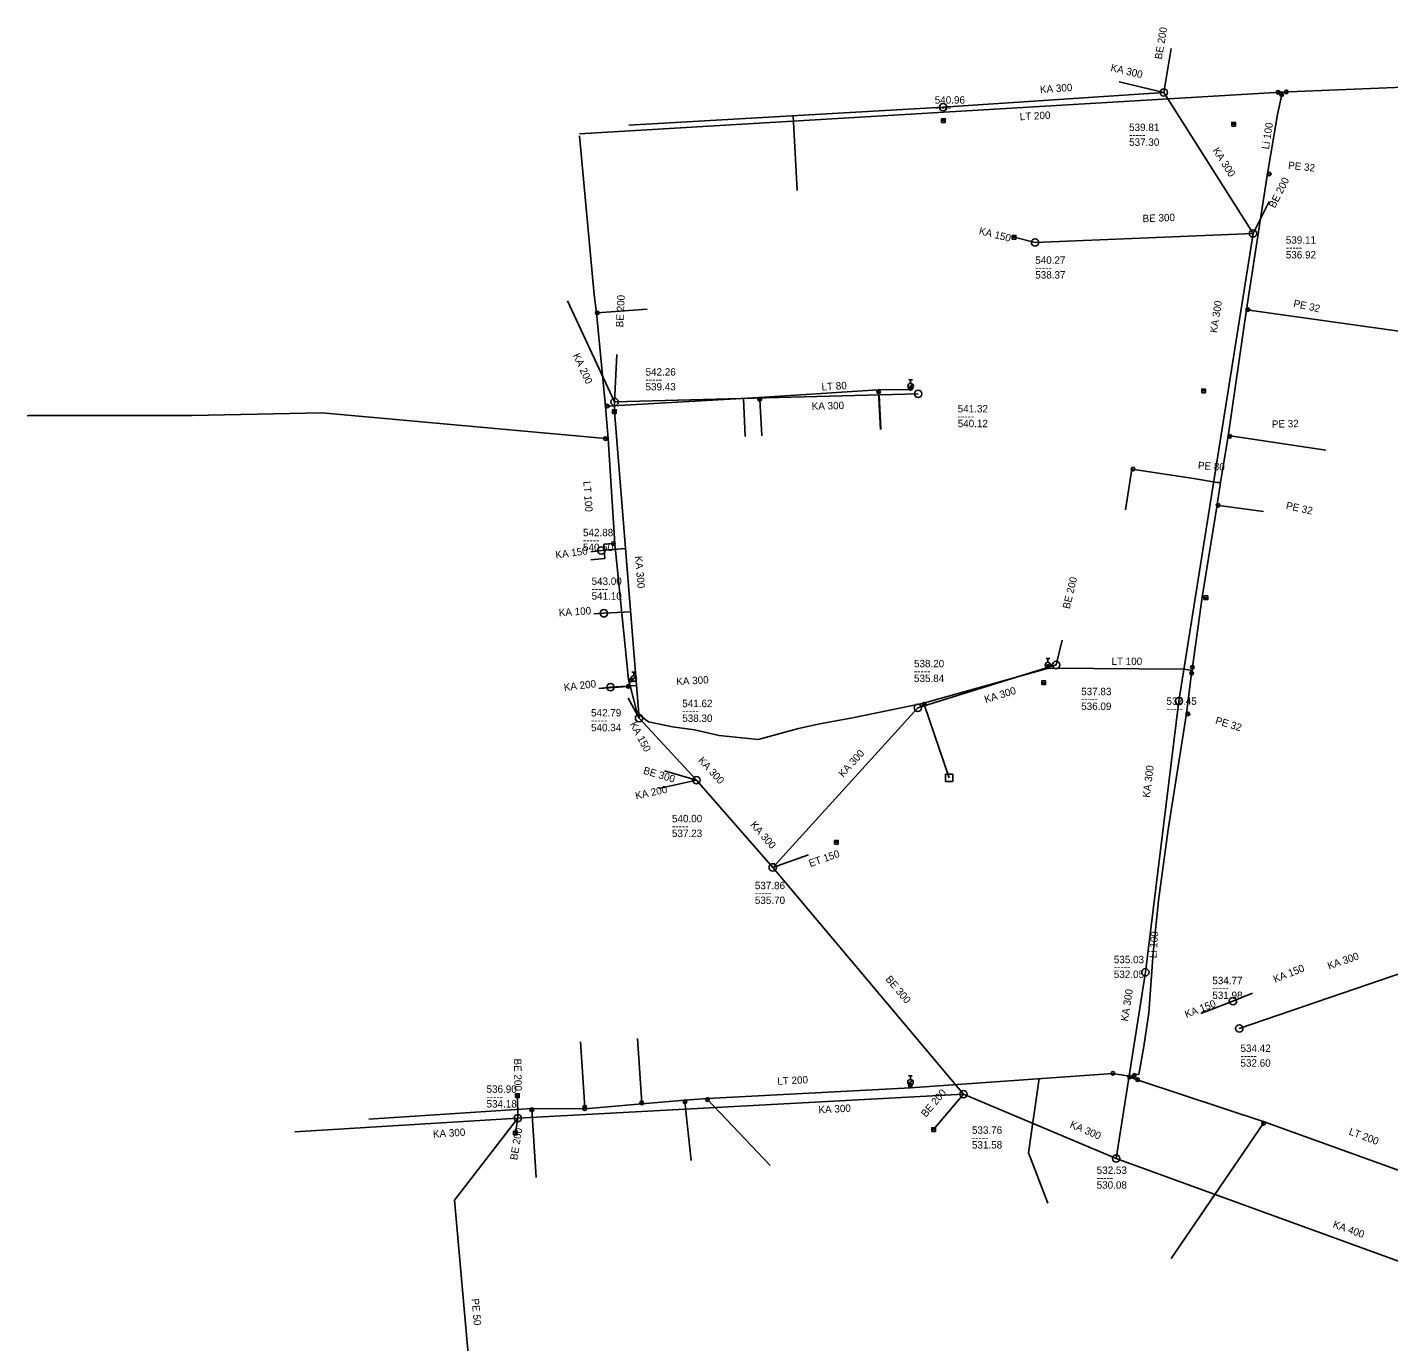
# Model space of a CAD drawing. Extents: x -769542 to -769122, y -1181691 to -1181360.
# Drawn here: x -769542.3 to -769357.9, y -1181565.1 to -1181387.2 of the extents above; entities that cross this region are included whole.
import ezdxf

# ---------------------------------------------------------------- set-up
doc = ezdxf.new("R2010")
doc.units = 0
for name, color, linetype in [('Level 19', 7, 'Continuous'), ('Level 20', 7, 'Continuous'), ('Level 21', 7, 'Continuous'), ('Level 24', 7, 'Continuous'), ('Level 26', 7, 'Continuous'), ('Level 29', 7, 'Continuous'), ('Level 40', 7, 'Continuous'), ('Level 41', 7, 'Continuous'), ('Level 44', 7, 'Continuous'), ('Level 45', 7, 'Continuous'), ('Level 46', 7, 'Continuous')]:
    doc.layers.add(name, color=color, linetype=linetype)

msp = doc.modelspace()

# ---------------------------------------------------------------- linework, layer by layer
at = {"layer": 'Level 19'}
for p, q in [((-769374.37, -1181406.99), (-769374.14, -1181407.02)), ((-769374.14, -1181407.02), (-769373.77, -1181407.06)), ((-769465.11, -1181425.84), (-769458.35, -1181425.35)), ((-769377.2, -1181425.36), (-769377.02, -1181425.4)), ((-769377.02, -1181425.4), (-769376.52, -1181425.51)), ((-769465.22, -1181425.84), (-769465.11, -1181425.84)), ((-769376.52, -1181425.51), (-769354.33, -1181428.62)), ((-769427.08, -1181436.27), (-769427.02, -1181436.51)), ((-769427.02, -1181436.51), (-769426.77, -1181441.63)), ((-769443.19, -1181437.28), (-769443.11, -1181437.54)), ((-769443.11, -1181437.54), (-769442.84, -1181442.46)), ((-769379.67, -1181442.54), (-769379.46, -1181442.54)), ((-769379.46, -1181442.54), (-769379.11, -1181442.53)), ((-769379.11, -1181442.53), (-769366.44, -1181444.44)), ((-769392.73, -1181446.98), (-769393.6, -1181452.52)), ((-769384.63, -1181448.22), (-769392.73, -1181446.98)), ((-769381.17, -1181448.78), (-769384.63, -1181448.22)), ((-769380.71, -1181448.81), (-769381.17, -1181448.78)), ((-769381.18, -1181451.84), (-769381.04, -1181451.87)), ((-769381.04, -1181451.87), (-769380.59, -1181451.97)), ((-769380.59, -1181451.97), (-769374.91, -1181452.73)), ((-769462.94, -1181457.07), (-769464.22, -1181457.16)), ((-769464.22, -1181457.16), (-769464.08, -1181459.08)), ((-769462.72, -1181457.08), (-769462.94, -1181457.07)), ((-769464.08, -1181459.08), (-769465.96, -1181459.25)), ((-769460.91, -1181476.41), (-769464.9, -1181476.7)), ((-769460.66, -1181476.32), (-769460.91, -1181476.41)), ((-769420.88, -1181478.68), (-769420.83, -1181478.83)), ((-769420.83, -1181478.83), (-769417.45, -1181488.77)), ((-769385.31, -1181480.09), (-769385.16, -1181480.13)), ((-769385.16, -1181480.13), (-769384.8, -1181480.24)), ((-769466.81, -1181533.35), (-769467.36, -1181524.5)), ((-769459.08, -1181532.77), (-769459.65, -1181524.04)), ((-769405.27, -1181529.49), (-769406.72, -1181539.56)), ((-769450.17, -1181532.2), (-769450.19, -1181532.33)), ((-769450.19, -1181532.33), (-769441.69, -1181541.27)), ((-769474, -1181533.53), (-769473.97, -1181533.72)), ((-769473.97, -1181533.72), (-769473.39, -1181542.86)), ((-769466.81, -1181533.35), (-769466.8, -1181533.57)), ((-769459.07, -1181532.92), (-769459.08, -1181532.77)), ((-769453.23, -1181532.43), (-769453.23, -1181532.62)), ((-769453.23, -1181532.62), (-769452.39, -1181540.56)), ((-769374.88, -1181535.54), (-769387.4, -1181553.86)), ((-769374.78, -1181535.36), (-769374.88, -1181535.54)), ((-769406.72, -1181539.56), (-769404.11, -1181546.34))]:
    msp.add_line(p, q, dxfattribs=at)
at = {"layer": 'Level 20'}
for p, q in [((-769321.1, -1181393.86), (-769371.45, -1181395.91)), ((-769372.37, -1181395.94), (-769372.92, -1181395.97)), ((-769372.37, -1181395.94), (-769372.42, -1181396.31)), ((-769371.8, -1181395.93), (-769372.37, -1181395.94)), ((-769371.45, -1181395.91), (-769371.8, -1181395.93)), ((-769373.3, -1181395.99), (-769467.51, -1181401.59)), ((-769372.92, -1181395.97), (-769373.3, -1181395.99)), ((-769372.42, -1181396.31), (-769373.01, -1181398.97)), ((-769373.01, -1181398.97), (-769374.37, -1181406.99)), ((-769465.53, -1181423.39), (-769467.51, -1181401.88)), ((-769374.37, -1181406.99), (-769377.2, -1181425.36)), ((-769465.22, -1181425.84), (-769465.53, -1181423.39)), ((-769377.2, -1181425.36), (-769379.67, -1181442.54)), ((-769464, -1181438.5), (-769465.22, -1181425.84)), ((-769443.19, -1181437.28), (-769427.08, -1181436.27)), ((-769427.08, -1181436.27), (-769422.72, -1181436.2)), ((-769422.72, -1181436.2), (-769422.68, -1181436.06)), ((-769422.68, -1181436.06), (-769422.68, -1181435.76)), ((-769463.77, -1181438.45), (-769443.19, -1181437.28)), ((-769542.3, -1181439.77), (-769542.1, -1181439.75)), ((-769542.1, -1181439.75), (-769519.98, -1181439.75)), ((-769519.98, -1181439.75), (-769502.36, -1181439.36)), ((-769502.36, -1181439.36), (-769464, -1181442.85)), ((-769464, -1181438.5), (-769463.77, -1181438.45)), ((-769463.65, -1181442.87), (-769464, -1181438.5)), ((-769464, -1181442.85), (-769463.65, -1181442.87)), ((-769463.65, -1181442.87), (-769462.72, -1181457.08)), ((-769379.67, -1181442.54), (-769380.71, -1181448.81)), ((-769380.71, -1181448.81), (-769381.18, -1181451.84)), ((-769381.18, -1181451.84), (-769383.2, -1181464.3)), ((-769462.72, -1181457.08), (-769460.86, -1181475.45)), ((-769383.2, -1181464.3), (-769384.51, -1181473.81)), ((-769419.81, -1181478.36), (-769404.02, -1181473.94)), ((-769404.1, -1181473.72), (-769404.08, -1181473.5)), ((-769404.02, -1181473.94), (-769404.1, -1181473.72)), ((-769404.02, -1181473.94), (-769385.64, -1181474.05)), ((-769384.57, -1181474.23), (-769385.64, -1181474.05)), ((-769384.62, -1181474.61), (-769385.31, -1181480.09)), ((-769384.57, -1181474.23), (-769384.62, -1181474.61)), ((-769384.51, -1181473.81), (-769384.57, -1181474.23)), ((-769460.86, -1181475.45), (-769460.66, -1181476.32)), ((-769460.86, -1181475.45), (-769460.52, -1181475.54)), ((-769460.66, -1181476.32), (-769459.71, -1181480.03)), ((-769460.52, -1181475.54), (-769460.18, -1181475.34)), ((-769420.88, -1181478.68), (-769430.57, -1181480.65)), ((-769420.88, -1181478.68), (-769419.81, -1181478.36)), ((-769458.15, -1181481.19), (-769459.71, -1181480.03)), ((-769430.57, -1181480.65), (-769434.95, -1181481.48)), ((-769385.31, -1181480.09), (-769387.82, -1181495.78)), ((-769454.93, -1181481.86), (-769458.15, -1181481.19)), ((-769451.93, -1181482.29), (-769454.93, -1181481.86)), ((-769448.59, -1181483.04), (-769451.93, -1181482.29)), ((-769437.84, -1181482.12), (-769443.3, -1181483.59)), ((-769434.95, -1181481.48), (-769437.84, -1181482.12)), ((-769443.3, -1181483.59), (-769448.59, -1181483.04)), ((-769387.82, -1181495.78), (-769389.13, -1181505.37)), ((-769389.13, -1181505.37), (-769389.84, -1181512.46)), ((-769389.84, -1181512.46), (-769390.4, -1181520.58)), ((-769390.4, -1181520.58), (-769391.1, -1181525.13)), ((-769391.1, -1181525.13), (-769391.76, -1181528.93)), ((-769422.73, -1181530.39), (-769422.7, -1181529.99)), ((-769422.71, -1181530.75), (-769422.73, -1181530.39)), ((-769422.71, -1181530.75), (-769395.28, -1181528.78)), ((-769395.28, -1181528.78), (-769393.37, -1181529.12)), ((-769393.37, -1181529.12), (-769393.03, -1181529.26)), ((-769393.03, -1181529.26), (-769392.5, -1181529.47)), ((-769392.38, -1181529.07), (-769392.5, -1181529.47)), ((-769392.5, -1181529.47), (-769391.95, -1181529.65)), ((-769392.25, -1181528.88), (-769392.38, -1181529.07)), ((-769391.76, -1181528.93), (-769392.25, -1181528.88)), ((-769391.95, -1181529.65), (-769391.6, -1181529.78)), ((-769391.6, -1181529.78), (-769374.78, -1181535.36)), ((-769453.23, -1181532.43), (-769450.17, -1181532.2)), ((-769450.17, -1181532.2), (-769422.71, -1181530.75)), ((-769496.05, -1181534.97), (-769474, -1181533.53)), ((-769474, -1181533.53), (-769466.8, -1181533.57)), ((-769466.8, -1181533.57), (-769459.06, -1181532.92)), ((-769459.06, -1181532.92), (-769453.23, -1181532.43)), ((-769374.78, -1181535.36), (-769346.68, -1181545.48))]:
    msp.add_line(p, q, dxfattribs=at)
at = {"layer": 'Level 21'}
for p, q in [((-769422.974, -1181435.991), (-769422.384, -1181435.528)), ((-769422.93, -1181434.885), (-769422.43, -1181434.885)), ((-769422.68, -1181435.385), (-769422.68, -1181434.885)), ((-769404.374, -1181473.731), (-769403.784, -1181473.268)), ((-769404.33, -1181472.625), (-769403.83, -1181472.625)), ((-769404.08, -1181473.125), (-769404.08, -1181472.625)), ((-769460.474, -1181475.571), (-769459.884, -1181475.108)), ((-769460.43, -1181474.465), (-769459.93, -1181474.465)), ((-769460.18, -1181474.965), (-769460.18, -1181474.465)), ((-769422.994, -1181530.221), (-769422.404, -1181529.758)), ((-769422.95, -1181529.115), (-769422.45, -1181529.115)), ((-769422.7, -1181529.615), (-769422.7, -1181529.115))]:
    msp.add_line(p, q, dxfattribs=at)
for centre in [(-769422.68, -1181435.76), (-769404.08, -1181473.5), (-769460.18, -1181475.34), (-769422.7, -1181529.99)]:
    msp.add_circle(centre, 0.375, dxfattribs=at)
at = {"layer": 'Level 26'}
for centre in [(-769372.92, -1181395.97), (-769371.8, -1181395.93), (-769372.42, -1181396.31), (-769374.14, -1181407.02), (-769377.02, -1181425.4), (-769377.02, -1181425.4), (-769465.11, -1181425.84), (-769427.02, -1181436.51), (-769422.68, -1181436.06), (-769463.77, -1181438.45), (-769443.11, -1181437.54), (-769464, -1181442.85), (-769379.46, -1181442.54), (-769392.55, -1181446.99), (-769381.04, -1181451.87), (-769462.94, -1181457.07), (-769404.1, -1181473.72), (-769384.62, -1181474.61), (-769384.51, -1181473.81), (-769460.91, -1181476.41), (-769460.52, -1181475.54), (-769420.83, -1181478.83), (-769385.16, -1181480.13), (-769385.16, -1181480.13), (-769395.28, -1181528.78), (-769422.73, -1181530.39), (-769393.03, -1181529.26), (-769392.38, -1181529.07), (-769391.95, -1181529.65), (-769453.23, -1181532.62), (-769450.19, -1181532.33), (-769473.97, -1181533.72), (-769466.81, -1181533.35), (-769466.8, -1181533.57), (-769459.08, -1181532.77), (-769374.88, -1181535.54)]:
    msp.add_circle(centre, 0.25, dxfattribs=at)
at = {"layer": 'Level 29'}
for p, q in [((-769416.95, -1181488.27), (-769417.95, -1181488.27)), ((-769417.95, -1181488.27), (-769417.95, -1181489.27)), ((-769417.95, -1181489.27), (-769416.95, -1181489.27)), ((-769416.95, -1181489.27), (-769416.95, -1181488.27))]:
    msp.add_line(p, q, dxfattribs=at)
at = {"layer": 'Level 40'}
for p, q in [((-769418.28, -1181398), (-769388.4, -1181396)), ((-769388.4, -1181396), (-769376.31, -1181415.1)), ((-769460.82, -1181400.43), (-769418.28, -1181398)), ((-769405.83, -1181416.3), (-769376.31, -1181415.1)), ((-769376.31, -1181415.1), (-769386.36, -1181478.4)), ((-769469.13, -1181424.2), (-769462.76, -1181437.9)), ((-769462.76, -1181437.9), (-769462.78, -1181439.2)), ((-769421.65, -1181436.8), (-769462.76, -1181437.9)), ((-769462.78, -1181439.2), (-769459.45, -1181480.7)), ((-769402.98, -1181473.5), (-769421.71, -1181479.3)), ((-769386.36, -1181478.4), (-769390.89, -1181515.1)), ((-769459.45, -1181480.7), (-769451.68, -1181489.1)), ((-769421.71, -1181479.3), (-769441.35, -1181500.9)), ((-769451.68, -1181489.1), (-769441.35, -1181500.9)), ((-769441.35, -1181500.9), (-769415.52, -1181531.6)), ((-769378.17, -1181522.7), (-769348.93, -1181512.7)), ((-769390.89, -1181515.1), (-769394.85, -1181540.3)), ((-769475.87, -1181534.84), (-769415.52, -1181531.6)), ((-769415.52, -1181531.6), (-769394.85, -1181540.3)), ((-769506.05, -1181536.7), (-769475.87, -1181534.84)), ((-769394.85, -1181540.3), (-769334.11, -1181562.4))]:
    msp.add_line(p, q, dxfattribs=at)
at = {"layer": 'Level 41'}
for centre in [(-769388.4, -1181396), (-769418.28, -1181398), (-769405.83, -1181416.3), (-769376.31, -1181415.1), (-769421.65, -1181436.8), (-769462.76, -1181437.9), (-769464.55, -1181458), (-769464.22, -1181466.5), (-769402.98, -1181473.5), (-769463.32, -1181476.5), (-769421.71, -1181479.3), (-769386.36, -1181478.4), (-769459.45, -1181480.7), (-769451.68, -1181489.1), (-769441.35, -1181500.9), (-769390.89, -1181515.1), (-769379.03, -1181519), (-769378.17, -1181522.7), (-769415.52, -1181531.6), (-769475.87, -1181534.84), (-769394.85, -1181540.3)]:
    msp.add_circle(centre, 0.5, dxfattribs=at)
at = {"layer": 'Level 45'}
for p, q in [((-769387.4, -1181390.06), (-769388.4, -1181396)), ((-769394.42, -1181394.57), (-769388.4, -1181396)), ((-769438.05, -1181409.28), (-769438.6, -1181399.16)), ((-769374.12, -1181410.76), (-769376.31, -1181415.1)), ((-769408.66, -1181415.6), (-769405.83, -1181416.3)), ((-769462.44, -1181431.46), (-769462.76, -1181437.9)), ((-769445.06, -1181442.57), (-769445.32, -1181437.43)), ((-769426.69, -1181441.63), (-769426.93, -1181436.94)), ((-769465.98, -1181458.19), (-769464.55, -1181458)), ((-769464.55, -1181458), (-769461.29, -1181457.72)), ((-769465.56, -1181466.58), (-769464.22, -1181466.5)), ((-769464.22, -1181466.5), (-769460.61, -1181466.29)), ((-769402.16, -1181470.16), (-769402.98, -1181473.5)), ((-769464.88, -1181476.68), (-769463.32, -1181476.5)), ((-769463.32, -1181476.5), (-769459.8, -1181476.29)), ((-769460.91, -1181477.98), (-769459.45, -1181480.7)), ((-769456, -1181487.81), (-769451.68, -1181489.1)), ((-769451.68, -1181489.1), (-769456.78, -1181490.2)), ((-769436.52, -1181499.2), (-769441.35, -1181500.9)), ((-769379.03, -1181519), (-769383.39, -1181520.68)), ((-769376.39, -1181517.93), (-769379.03, -1181519)), ((-769475.92, -1181531.8), (-769475.87, -1181534.84)), ((-769419.56, -1181536.4), (-769415.52, -1181531.6)), ((-769475.87, -1181534.84), (-769484.42, -1181545.93)), ((-769476.19, -1181536.84), (-769475.87, -1181534.84)), ((-769484.42, -1181545.93), (-769481.6, -1181577.74))]:
    msp.add_line(p, q, dxfattribs=at)
at = {"layer": 'Level 46'}
for p, q in [((-769418.49, -1181399.8), (-769417.99, -1181399.8)), ((-769379.2, -1181400.3), (-769378.7, -1181400.3)), ((-769408.91, -1181415.6), (-769408.41, -1181415.6)), ((-769383.26, -1181436.4), (-769382.76, -1181436.4)), ((-769463.03, -1181439.2), (-769462.53, -1181439.2)), ((-769382.95, -1181464.4), (-769382.45, -1181464.4)), ((-769404.91, -1181475.9), (-769404.41, -1181475.9)), ((-769432.97, -1181497.5), (-769432.47, -1181497.5)), ((-769476.17, -1181531.8), (-769475.67, -1181531.8)), ((-769476.44, -1181536.84), (-769475.94, -1181536.84)), ((-769419.81, -1181536.4), (-769419.31, -1181536.4))]:
    msp.add_line(p, q, dxfattribs=at)
for points in [[(-769418.49, -1181400.051), (-769417.9895, -1181400.051), (-769417.9895, -1181399.5495), (-769418.49, -1181399.5495)], [(-769379.2, -1181400.551), (-769378.6995, -1181400.551), (-769378.6995, -1181400.0495), (-769379.2, -1181400.0495)], [(-769408.91, -1181415.851), (-769408.4095, -1181415.851), (-769408.4095, -1181415.3495), (-769408.91, -1181415.3495)], [(-769383.26, -1181436.651), (-769382.7595, -1181436.651), (-769382.7595, -1181436.1495), (-769383.26, -1181436.1495)], [(-769463.03, -1181439.451), (-769462.5295, -1181439.451), (-769462.5295, -1181438.9495), (-769463.03, -1181438.9495)], [(-769382.95, -1181464.651), (-769382.4495, -1181464.651), (-769382.4495, -1181464.1495), (-769382.95, -1181464.1495)], [(-769404.91, -1181476.151), (-769404.4095, -1181476.151), (-769404.4095, -1181475.6495), (-769404.91, -1181475.6495)], [(-769432.97, -1181497.751), (-769432.4695, -1181497.751), (-769432.4695, -1181497.2495), (-769432.97, -1181497.2495)], [(-769476.17, -1181532.051), (-769475.6695, -1181532.051), (-769475.6695, -1181531.5495), (-769476.17, -1181531.5495)], [(-769476.44, -1181537.091), (-769475.9395, -1181537.091), (-769475.9395, -1181536.5895), (-769476.44, -1181536.5895)], [(-769419.81, -1181536.651), (-769419.3095, -1181536.651), (-769419.3095, -1181536.1495), (-769419.81, -1181536.1495)]]:
    msp.add_lwpolyline(points, close=True, dxfattribs=at)

# ---------------------------------------------------------------- texts
at = {"layer": 'Level 24'}
for s, rotation, p in [('LT 200', 2.981, (-769407.88, -1181399.77)), ('Li 100', 81.242, (-769374.16, -1181403.75)), ('PE 32', 353.83, (-769371.6, -1181406.33)), ('PE 32', 347.593, (-769370.91, -1181425)), ('LT 80', 3.587, (-769434.71, -1181436.36)), ('PE 32', 1.637, (-769373.75, -1181441.4)), ('PE 80', 356.269, (-769383.8, -1181446.97)), ('LT 100', 273.895, (-769467, -1181448.65)), ('PE 32', 347.471, (-769371.91, -1181452.36)), ('PE 32', 343.009, (-769381.5, -1181481.43)), ('Li 100', 86.055, (-769389.39, -1181513.22)), ('LT 200', 3.023, (-769440.71, -1181530.34)), ('LT 200', 339.594, (-769363.42, -1181537.04))]:
    msp.add_text(s, height=1, rotation=rotation, dxfattribs=at).set_placement(p)
msp.add_text('LT 100', height=1, dxfattribs=at).set_placement((-769395.48, -1181473.5))
at = {"layer": 'Level 44'}
for s, rotation, p in [('BE 200', 80.456, (-769388.66, -1181391.57)), ('KA 300', 346.591, (-769395.66, -1181393.07)), ('KA 300', 3.829, (-769405.13, -1181396.09)), ('KA 300', 302.333, (-769381.82, -1181403.84)), ('BE 200', 63.198, (-769373.35, -1181411.73)), ('BE 300', 2.328, (-769391.25, -1181413.57)), ('KA 150', 346.107, (-769413.49, -1181415.18)), ('BE 200', 87.171, (-769461.6, -1181427.81)), ('KA 300', 80.979, (-769381.19, -1181428.6)), ('KA 200', 294.937, (-769468.44, -1181431.59)), ('KA 300', 1.533, (-769436.06, -1181438.97)), ('KA 150', 7.658, (-769470.71, -1181459.1)), ('KA 300', 274.588, (-769460, -1181458.78)), ('BE 200', 76.275, (-769401.15, -1181465.98)), ('KA 100', 3.555, (-769470.29, -1181466.91)), ('KA 300', 3.353, (-769454.38, -1181476.24)), ('KA 200', 6.638, (-769469.58, -1181477.02)), ('KA 300', 17.206, (-769412.51, -1181478.67)), ('KA 150', 298.227, (-769460.74, -1181481.51)), ('KA 300', 312.769, (-769451.52, -1181486.49)), ('KA 300', 47.721, (-769431.82, -1181488.77)), ('BE 300', 343.381, (-769458.96, -1181488.2)), ('KA 300', 82.963, (-769390.29, -1181491.5)), ('KA 200', 12.132, (-769459.85, -1181491.7)), ('KA 300', 311.2, (-769444.45, -1181495.19)), ('ET 150', 19.356, (-769436.26, -1181500.87)), ('KA 300', 18.881, (-769366.03, -1181514.73)), ('BE 300', 310.076, (-769426.14, -1181516.07)), ('KA 150', 22.007, (-769373.32, -1181516.55)), ('KA 300', 81.069, (-769393.25, -1181521.79)), ('KA 150', 21.111, (-769385.33, -1181521.3)), ('BE 200', 270.942, (-769476.39, -1181526.78)), ('BE 200', 49.914, (-769420.61, -1181534.8)), ('KA 300', 3.073, (-769435.13, -1181534.21)), ('KA 300', 337.174, (-769401.2, -1181536.07)), ('KA 300', 3.527, (-769487.33, -1181537.49)), ('BE 200', 80.91, (-769475.95, -1181540.58)), ('KA 400', 340.006, (-769365.58, -1181549.6)), ('PE 50', 275.066, (-769482.13, -1181559.31))]:
    msp.add_text(s, height=1, rotation=rotation, dxfattribs=at).set_placement(p)
for s, p in [('540.96', (-769419.41, -1181397.51)), ('-----', (-769419.41, -1181398.51)), ('539.81', (-769393.09, -1181401.22)), ('537.30', (-769393.09, -1181403.22)), ('-----', (-769393.09, -1181402.22)), ('539.11', (-769371.87, -1181416.47)), ('536.92', (-769371.87, -1181418.47)), ('-----', (-769371.87, -1181417.47)), ('540.27', (-769405.8, -1181419.19)), ('-----', (-769405.8, -1181420.19)), ('538.37', (-769405.8, -1181421.19)), ('542.26', (-769458.57, -1181434.33)), ('539.43', (-769458.57, -1181436.33)), ('-----', (-769458.57, -1181435.33)), ('541.32', (-769416.3, -1181439.31)), ('-----', (-769416.3, -1181440.31)), ('540.12', (-769416.3, -1181441.31)), ('542.88', (-769467.04, -1181456.07)), ('-----', (-769467.04, -1181457.07)), ('540.60', (-769467.04, -1181458.07)), ('543.00', (-769465.88, -1181462.66)), ('541.10', (-769465.88, -1181464.66)), ('-----', (-769465.88, -1181463.66)), ('538.20', (-769422.22, -1181473.81)), ('535.84', (-769422.22, -1181475.81)), ('-----', (-769422.22, -1181474.81)), ('537.83', (-769399.58, -1181477.59)), ('541.62', (-769453.6, -1181479.21)), ('536.09', (-769399.58, -1181479.59)), ('-----', (-769399.58, -1181478.59)), ('537.45', (-769388.03, -1181478.89)), ('542.79', (-769465.95, -1181480.47)), ('538.30', (-769453.6, -1181481.21)), ('-----', (-769453.6, -1181480.21)), ('-----', (-769388.03, -1181479.89)), ('540.34', (-769465.95, -1181482.47)), ('-----', (-769465.95, -1181481.47)), ('540.00', (-769454.99, -1181494.79)), ('-----', (-769454.99, -1181495.79)), ('537.23', (-769454.99, -1181496.79)), ('537.86', (-769443.77, -1181503.85)), ('-----', (-769443.77, -1181504.85)), ('535.70', (-769443.77, -1181505.85)), ('535.03', (-769395.16, -1181513.87)), ('532.05', (-769395.16, -1181515.87)), ('-----', (-769395.16, -1181514.87)), ('534.77', (-769381.82, -1181516.71)), ('-----', (-769381.82, -1181517.71)), ('531.98', (-769381.82, -1181518.71)), ('534.42', (-769378.01, -1181525.88)), ('532.60', (-769378.01, -1181527.88)), ('-----', (-769378.01, -1181526.88)), ('536.90', (-769480.1, -1181531.41)), ('534.18', (-769480.1, -1181533.41)), ('-----', (-769480.1, -1181532.41)), ('533.76', (-769414.37, -1181536.96)), ('-----', (-769414.37, -1181537.96)), ('531.58', (-769414.37, -1181538.96)), ('532.53', (-769397.48, -1181542.39)), ('530.08', (-769397.48, -1181544.39)), ('-----', (-769397.48, -1181543.39))]:
    msp.add_text(s, height=1, dxfattribs=at).set_placement(p)

doc.saveas('drawing.dxf')
